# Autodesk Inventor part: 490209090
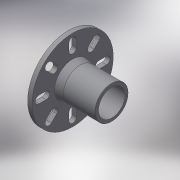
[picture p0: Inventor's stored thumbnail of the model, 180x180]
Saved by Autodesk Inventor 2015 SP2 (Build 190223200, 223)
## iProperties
Created: 2017-07
Part Number: 490209090
Material: Generic
Description: PLASSON FULL FACE FLANGE 90
Document SubType Name: Modeling
Designer: Кирилл
Density: 1 g/cm^3
Appearance: Default
Author: Кирилл
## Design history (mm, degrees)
derived "490209.ipt"
feature "Solid1::490209.ipt"
tag "TaggingFeature1"
body "Solid1"
other parameters: "d0" = 118, "d1" = 98, "d3" = 72, "d5" = 12, "d6" = 86, "d9" = 81.5, "d12" = 0, "d14" = 360 deg, "d17" = 0.9, "d18" = 0.9, "d19" = 0.9, "d20" = 0.9, "d21" = 0.9, "d22" = 0.9, "d23" = 0.9, "d24" = 0.9, "d25" = 0.9, "d26" = 0.9, "d27" = 0, "d28" = 0.9, "d29" = 0.9, "d30" = 0.9, "d31" = 0.9, "d32" = 0.9, "L_" = 118, "L_1" = 86, "D_1" = 98, "a_" = 12, "Dp_" = 163
